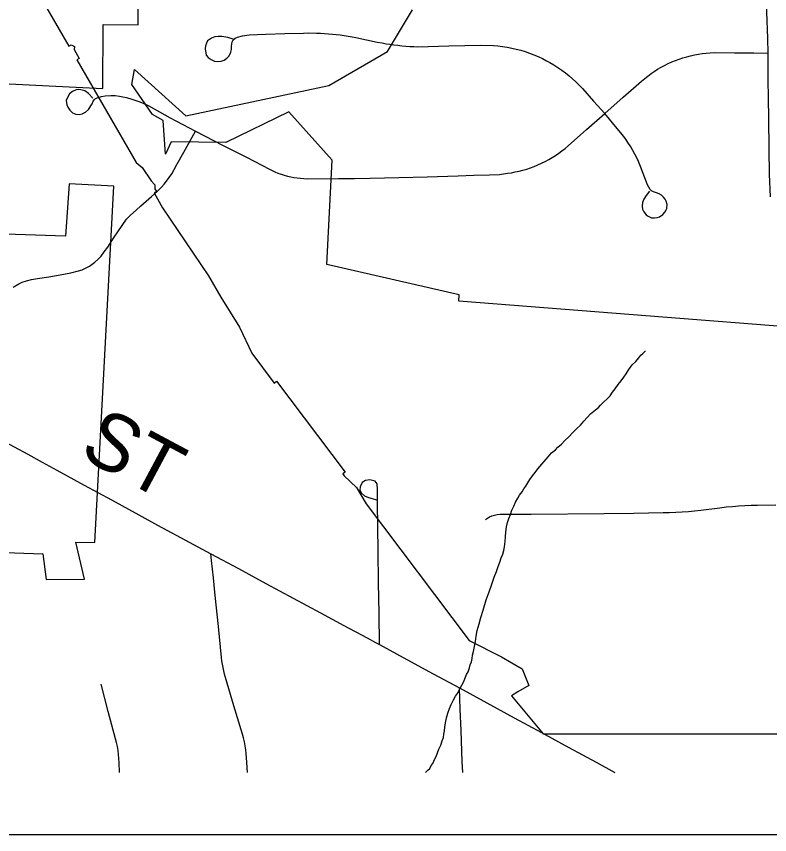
# Model space of a CAD drawing. Extents: x -11.4 to 84.1, y 11.1 to 59.
# Drawn here: x 27.855 to 28.606, y 40.548 to 41.365 of the extents above; entities that cross this region are included whole.
import ezdxf

# ---------------------------------------------------------------- set-up
doc = ezdxf.new("R2010")
doc.units = 0
for name, color, linetype in [('GM_X_Corporation', 7, 'Continuous'), ('GM_X_County_Road', 7, 'Continuous'), ('GM_X_County_Road_Text', 7, 'Continuous'), ('GM_X_Minor_River', 7, 'Continuous'), ('GM_X_State_Route', 7, 'Continuous'), ('GM_X_Township_Road', 7, 'Continuous'), ('SH_Data', 7, 'Continuous')]:
    doc.layers.add(name, color=color, linetype=linetype)

msp = doc.modelspace()

# ---------------------------------------------------------------- linework, layer by layer
at = {"layer": 'GM_X_Corporation'}
msp.add_line((28.38022, 40.64894), (28.7042, 40.64894), dxfattribs=at)
for points in [[(27.61954, 41.30861), (27.94083, 41.29266), (27.94109, 41.35655), (27.97612, 41.35641), (27.9768, 41.52229)], [(27.86218, 41.41224), (27.90679, 41.335), (27.90923, 41.33647), (27.91254, 41.33463), (27.91217, 41.33163), (27.91729, 41.32277), (27.91486, 41.32131), (27.97405, 41.21881), (27.98017, 41.21403), (27.98917, 41.20069), (27.99265, 41.19669), (27.99287, 41.19253), (27.99433, 41.1901), (27.9919, 41.18863), (28.00042, 41.17387), (28.04639, 41.10575), (28.05861, 41.08459), (28.07738, 41.05456), (28.08939, 41.02882), (28.11196, 40.99888), (28.1142, 41.00063), (28.18259, 40.9099), (28.18035, 40.90815), (28.18172, 40.90634), (28.19385, 40.89463), (28.2037, 40.87824), (28.30629, 40.74215), (28.33869, 40.72566), (28.3592, 40.71383), (28.36594, 40.69715), (28.35495, 40.6908), (28.34868, 40.68689), (28.38022, 40.64894)], [(28.83069, 41.03869), (28.29615, 41.0805), (28.29648, 41.08674), (28.16435, 41.1172), (28.1698, 41.22141), (28.12646, 41.26953), (28.06348, 41.2388), (28.00913, 41.23973), (28.00337, 41.22737), (28.00103, 41.26081), (27.99053, 41.26687), (27.96967, 41.29665), (27.97233, 41.31176), (28.02371, 41.26552), (28.16653, 41.29591), (28.22508, 41.32973), (28.25005, 41.3713)], [(27.72962, 40.8338), (27.88101, 40.82851), (27.88435, 40.80288), (27.92236, 40.80317), (27.91387, 40.84002), (27.93281, 40.83985), (27.95178, 41.19544), (27.90723, 41.19764), (27.90359, 41.14549), (27.84377, 41.14758)]]:
    msp.add_lwpolyline(points, dxfattribs=at)
at = {"layer": 'GM_X_County_Road'}
msp.add_lwpolyline([(27.83857, 40.94268), (27.86585, 40.92782), (27.88036, 40.91992), (27.89487, 40.91201), (27.92215, 40.89714), (27.94943, 40.88228), (27.97671, 40.86742), (27.99541, 40.85723), (28.01411, 40.84704), (28.03142, 40.83773), (28.04873, 40.82841), (28.07609, 40.81369), (28.10345, 40.79897), (28.13081, 40.78426), (28.15817, 40.76954), (28.18139, 40.75705), (28.20461, 40.74456), (28.21281, 40.74015), (28.21707, 40.73785), (28.24438, 40.72302), (28.27051, 40.70884), (28.29665, 40.69465), (28.32395, 40.67982), (28.35125, 40.66499), (28.37855, 40.65016), (28.40586, 40.63532), (28.43316, 40.62049), (28.452, 40.61026)], dxfattribs=at)
at = {"layer": 'GM_X_Minor_River'}
for points in [[(28.27488, 40.62977), (28.27633, 40.63359), (28.27817, 40.63742), (28.27961, 40.64201), (28.2807, 40.64507), (28.28102, 40.6485), (28.28172, 40.65193), (28.28204, 40.65536), (28.28272, 40.65994), (28.28378, 40.6649), (28.28522, 40.66948), (28.28667, 40.67407), (28.28849, 40.67828), (28.2907, 40.68288), (28.29292, 40.68634), (28.29477, 40.68903), (28.29919, 40.69747), (28.30103, 40.70092), (28.30248, 40.70475), (28.30394, 40.7082), (28.30542, 40.71088), (28.30615, 40.7128), (28.30687, 40.71471), (28.30758, 40.71777), (28.30867, 40.72082), (28.30938, 40.72388), (28.3097, 40.72731), (28.31078, 40.73113), (28.31183, 40.73609), (28.31289, 40.74105), (28.31356, 40.74638), (28.3146, 40.7521), (28.31639, 40.7586), (28.31818, 40.76509), (28.32034, 40.77235), (28.32358, 40.78267), (28.32649, 40.7907), (28.32902, 40.79835), (28.33156, 40.80524), (28.33374, 40.81098), (28.33556, 40.81595), (28.33701, 40.82016), (28.33846, 40.82437), (28.33991, 40.82819), (28.34099, 40.83163), (28.34169, 40.83545), (28.34236, 40.84078), (28.34266, 40.84535), (28.34296, 40.8503), (28.34363, 40.85525), (28.3447, 40.85983), (28.34615, 40.86366), (28.3476, 40.86787), (28.34905, 40.87207), (28.35088, 40.87591), (28.35271, 40.88012), (28.35493, 40.88396), (28.35677, 40.88703), (28.35937, 40.89049), (28.36085, 40.89318), (28.36308, 40.89588), (28.36492, 40.89933), (28.36715, 40.90279), (28.36974, 40.90626), (28.37234, 40.90972), (28.37495, 40.91319), (28.38538, 40.92515), (28.38873, 40.92938), (28.39248, 40.93211), (28.39509, 40.93481), (28.39846, 40.93791), (28.40182, 40.94139), (28.40593, 40.94526), (28.41004, 40.94951), (28.41377, 40.95337), (28.41751, 40.95685), (28.42086, 40.96071), (28.42422, 40.96457), (28.42758, 40.96805), (28.43244, 40.97231), (28.43544, 40.97464), (28.43768, 40.97696), (28.44068, 40.97967), (28.44404, 40.98315), (28.44702, 40.98624), (28.44962, 40.9897), (28.45222, 40.99317), (28.45519, 40.9974), (28.45816, 41.00125), (28.46076, 41.00472), (28.46299, 41.00818), (28.46595, 41.01241), (28.46929, 41.01703), (28.47265, 41.0205), (28.47563, 41.02398), (28.47787, 41.02667), (28.47974, 41.02823), (28.48198, 41.03055), (28.48236, 41.03055)], [(28.26277, 40.61026), (28.26529, 40.6125), (28.26716, 40.61443), (28.26863, 40.61711), (28.27011, 40.61942), (28.27121, 40.62172), (28.27231, 40.62402), (28.27341, 40.62632), (28.27488, 40.62977)]]:
    msp.add_lwpolyline(points, dxfattribs=at)
at = {"layer": 'GM_X_State_Route'}
msp.add_lwpolyline([(28.6071, 41.18474), (28.60621, 41.20718), (28.60589, 41.23227), (28.6055, 41.26334), (28.60525, 41.28279), (28.605, 41.30224), (28.60479, 41.32814), (28.60447, 41.34277), (28.60371, 41.3693), (28.60346, 41.39028), (28.60321, 41.41126), (28.60313, 41.41804)], dxfattribs=at)
at = {"layer": 'GM_X_Township_Road'}
for points in [[(28.07091, 41.34187), (28.06553, 41.34368), (28.05952, 41.34451), (28.0558, 41.34477), (28.05265, 41.34436), (28.04944, 41.34311), (28.04722, 41.34177), (28.04535, 41.34022), (28.04431, 41.33799), (28.04339, 41.33525), (28.04292, 41.3323), (28.04411, 41.3262), (28.04592, 41.32361), (28.04887, 41.3216), (28.05218, 41.32004), (28.05532, 41.31961), (28.05908, 41.32012), (28.06184, 41.32113), (28.06459, 41.32309), (28.06679, 41.32522), (28.06848, 41.32894), (28.0691, 41.33157), (28.06935, 41.33453), (28.06957, 41.33742), (28.07003, 41.3394), (28.07101, 41.3412), (28.07277, 41.34296), (28.07529, 41.34406), (28.08037, 41.34539), (28.08674, 41.34647), (28.10346, 41.34705), (28.12234, 41.34759), (28.14123, 41.34813), (28.14612, 41.34821), (28.15403, 41.34812), (28.15801, 41.34797), (28.16199, 41.34775), (28.16592, 41.34747), (28.1699, 41.34711), (28.17383, 41.34668), (28.17776, 41.3462), (28.1817, 41.34562), (28.18563, 41.345), (28.18951, 41.34429), (28.19344, 41.34354), (28.21476, 41.33913), (28.21955, 41.33819), (28.22348, 41.3375), (28.22741, 41.3369), (28.23135, 41.33634), (28.23527, 41.33586), (28.23921, 41.33546), (28.24319, 41.33512), (28.24712, 41.33484), (28.2511, 41.33464), (28.25508, 41.33451), (28.28614, 41.33521), (28.302, 41.33556), (28.31785, 41.33592), (28.3306, 41.33567), (28.3352, 41.33526), (28.33979, 41.33471), (28.34439, 41.33399), (28.34893, 41.33311), (28.35343, 41.33208), (28.35793, 41.33088), (28.36234, 41.32954), (28.3667, 41.32803), (28.37105, 41.32639), (28.37532, 41.32457), (28.37949, 41.32263), (28.38366, 41.32053), (28.38711, 41.31861), (28.39109, 41.31625), (28.39502, 41.31375), (28.39881, 41.31112), (28.40255, 41.30835), (28.40615, 41.30546), (28.40965, 41.30246), (28.41307, 41.29931), (28.41638, 41.29606), (28.41955, 41.29269), (28.43071, 41.2803), (28.44188, 41.2679)], [(27.93093, 41.28312), (27.92635, 41.28795), (27.9227, 41.29033), (27.91891, 41.29145), (27.91673, 41.29164), (27.91429, 41.29132), (27.91058, 41.28982), (27.9077, 41.28753), (27.90577, 41.28446), (27.90434, 41.2808), (27.90498, 41.27634), (27.90577, 41.27429), (27.90774, 41.27129), (27.9105, 41.26846), (27.91381, 41.26719), (27.91729, 41.26672), (27.92018, 41.26748), (27.92344, 41.26932), (27.92635, 41.27182), (27.93013, 41.27743), (27.93132, 41.28021), (27.93243, 41.2817), (27.93345, 41.28265), (27.936, 41.28395), (27.93937, 41.28496), (27.94329, 41.28552), (27.9489, 41.28575), (27.95327, 41.28564), (27.95753, 41.28518), (27.96078, 41.28462), (27.96437, 41.28384), (27.9699, 41.28221), (27.97391, 41.28081), (27.97768, 41.27955), (27.98175, 41.27778), (27.98658, 41.27555), (28.00819, 41.26337), (28.03338, 41.25025), (28.061, 41.23602), (28.08406, 41.22415), (28.10712, 41.21227), (28.11254, 41.20969), (28.11561, 41.20831), (28.11874, 41.20724), (28.12187, 41.20627), (28.12509, 41.20544), (28.12831, 41.2047), (28.13153, 41.20407), (28.1348, 41.20356), (28.13812, 41.20317), (28.14138, 41.20288), (28.14501, 41.20253), (28.17607, 41.20293), (28.19189, 41.20314), (28.20771, 41.20335), (28.2361, 41.20406), (28.26448, 41.20478), (28.29554, 41.2057), (28.31116, 41.20616), (28.32678, 41.20662), (28.33682, 41.20703), (28.34463, 41.20818), (28.34857, 41.20875), (28.35245, 41.20948), (28.35634, 41.21033), (28.36017, 41.21131), (28.36396, 41.21242), (28.36776, 41.21368), (28.37145, 41.21506), (28.37515, 41.21656), (28.37875, 41.21821), (28.38231, 41.21997), (28.38581, 41.22185), (28.38922, 41.22385), (28.39259, 41.22598), (28.39586, 41.22822), (28.39908, 41.23058), (28.40216, 41.23304), (28.4052, 41.2356), (28.42354, 41.25175), (28.44188, 41.2679), (28.46025, 41.28406), (28.47861, 41.30021), (28.48165, 41.30277), (28.48473, 41.30524), (28.48795, 41.3076), (28.49122, 41.30983), (28.49458, 41.31196), (28.49799, 41.31396), (28.5015, 41.31584), (28.50506, 41.31761), (28.50866, 41.31924), (28.51235, 41.32075), (28.51605, 41.32214), (28.51984, 41.32338), (28.52363, 41.3245), (28.52747, 41.32548), (28.53136, 41.32634), (28.53524, 41.32704), (28.53917, 41.32762), (28.54316, 41.32806), (28.54709, 41.32837), (28.55168, 41.32854), (28.57114, 41.32839), (28.59061, 41.32824), (28.60479, 41.32814)], [(28.48655, 41.19032), (28.48302, 41.18594), (28.48063, 41.18235), (28.47937, 41.17904), (28.47924, 41.17528), (28.47961, 41.17234), (28.48079, 41.16981), (28.48312, 41.16678), (28.48505, 41.16532), (28.48836, 41.16382), (28.49136, 41.16359), (28.49404, 41.1639), (28.49634, 41.16477), (28.49969, 41.16715), (28.50177, 41.16927), (28.50311, 41.17155), (28.50359, 41.17321), (28.50406, 41.17692), (28.50319, 41.18023), (28.50201, 41.18251), (28.50043, 41.18448), (28.49844, 41.18636), (28.49594, 41.1878), (28.49357, 41.18874), (28.49041, 41.18953), (28.48836, 41.19073), (28.48708, 41.19211), (28.48447, 41.19656), (28.47753, 41.21483), (28.47545, 41.21978), (28.47372, 41.22359), (28.47188, 41.22727), (28.46991, 41.23084), (28.46796, 41.23442), (28.46496, 41.23903), (28.46266, 41.24238), (28.46046, 41.24537), (28.4577, 41.24871), (28.45424, 41.25298), (28.44188, 41.2679)], [(27.85148, 41.09452), (27.85696, 41.09783), (27.86042, 41.09942), (27.86459, 41.10086), (27.86964, 41.10215), (27.87569, 41.10331), (27.88682, 41.10499), (27.89822, 41.10687), (27.90884, 41.10892), (27.91647, 41.1108), (27.92022, 41.11195), (27.92368, 41.11354), (27.92743, 41.11555), (27.93011, 41.11737), (27.93267, 41.11938), (27.93578, 41.12204), (27.9391, 41.1255), (27.9423, 41.1298), (27.94587, 41.13458), (27.94927, 41.13976), (27.95228, 41.14434), (27.95574, 41.14961), (27.95997, 41.15606), (27.96446, 41.16254), (27.96843, 41.16633), (27.97394, 41.17122), (27.97887, 41.17579), (27.98418, 41.18031), (27.98935, 41.1849), (27.99516, 41.19006), (27.99924, 41.19434), (28.00198, 41.19722), (28.00453, 41.20043), (28.00707, 41.20393), (28.00957, 41.20764), (28.01477, 41.21695), (28.02169, 41.22933), (28.02836, 41.24126), (28.03338, 41.25025)], [(28.21707, 40.73785), (28.21659, 40.76891), (28.2161, 40.79997), (28.21562, 40.83104), (28.21524, 40.85528), (28.21487, 40.87953), (28.21496, 40.88526), (28.21487, 40.89256), (28.21461, 40.89832), (28.21256, 40.90098), (28.20717, 40.90234), (28.20282, 40.90157), (28.19974, 40.89969), (28.19752, 40.89542), (28.19735, 40.89209), (28.19906, 40.88901), (28.20205, 40.88636), (28.20589, 40.88465), (28.20974, 40.88354), (28.21393, 40.88226)], [(28.32269, 40.86272), (28.32486, 40.8642), (28.3268, 40.86535), (28.3292, 40.86638), (28.33172, 40.86706), (28.33446, 40.86763), (28.33743, 40.86795), (28.36849, 40.86803), (28.44133, 40.86866), (28.47068, 40.86915), (28.50002, 40.86964), (28.50632, 40.86977), (28.51263, 40.87001), (28.51893, 40.87037), (28.52523, 40.87085), (28.53148, 40.87145), (28.53778, 40.87217), (28.5566, 40.87451), (28.56285, 40.87523), (28.56915, 40.87584), (28.5754, 40.87633), (28.58171, 40.87673), (28.58801, 40.877), (28.59436, 40.87717), (28.6125, 40.87748)], [(28.08533, 40.61026), (28.08432, 40.62509), (28.08399, 40.62907), (28.08347, 40.63305), (28.08285, 40.63699), (28.08205, 40.64093), (28.0811, 40.64481), (28.08006, 40.64868), (28.07164, 40.67692), (28.06322, 40.70518), (28.06232, 40.70845), (28.06152, 40.71174), (28.06081, 40.71506), (28.0602, 40.71839), (28.05967, 40.72174), (28.0593, 40.72512), (28.05614, 40.75602), (28.05298, 40.78693), (28.05119, 40.80445), (28.0494, 40.82198), (28.04873, 40.82841)], [(27.95755, 40.61026), (27.95715, 40.62033), (27.95692, 40.62432), (27.95654, 40.62831), (27.95602, 40.63228), (27.95531, 40.63622), (27.95451, 40.64014), (27.95356, 40.64403), (27.9463, 40.67121), (27.93904, 40.69839)], [(28.30001, 40.61026), (28.29958, 40.62116), (28.29834, 40.6522), (28.29749, 40.67343), (28.29665, 40.69465)]]:
    msp.add_lwpolyline(points, dxfattribs=at)
at = {"layer": 'SH_Data'}
msp.add_line((26.16529, 40.54828), (33.16529, 40.54828), dxfattribs=at)

# ---------------------------------------------------------------- texts
at = {"layer": 'GM_X_County_Road_Text'}
msp.add_text('ST', height=0.056818, rotation=331.86029, dxfattribs=at).set_placement((27.91575, 40.92644))

doc.saveas('drawing.dxf')
